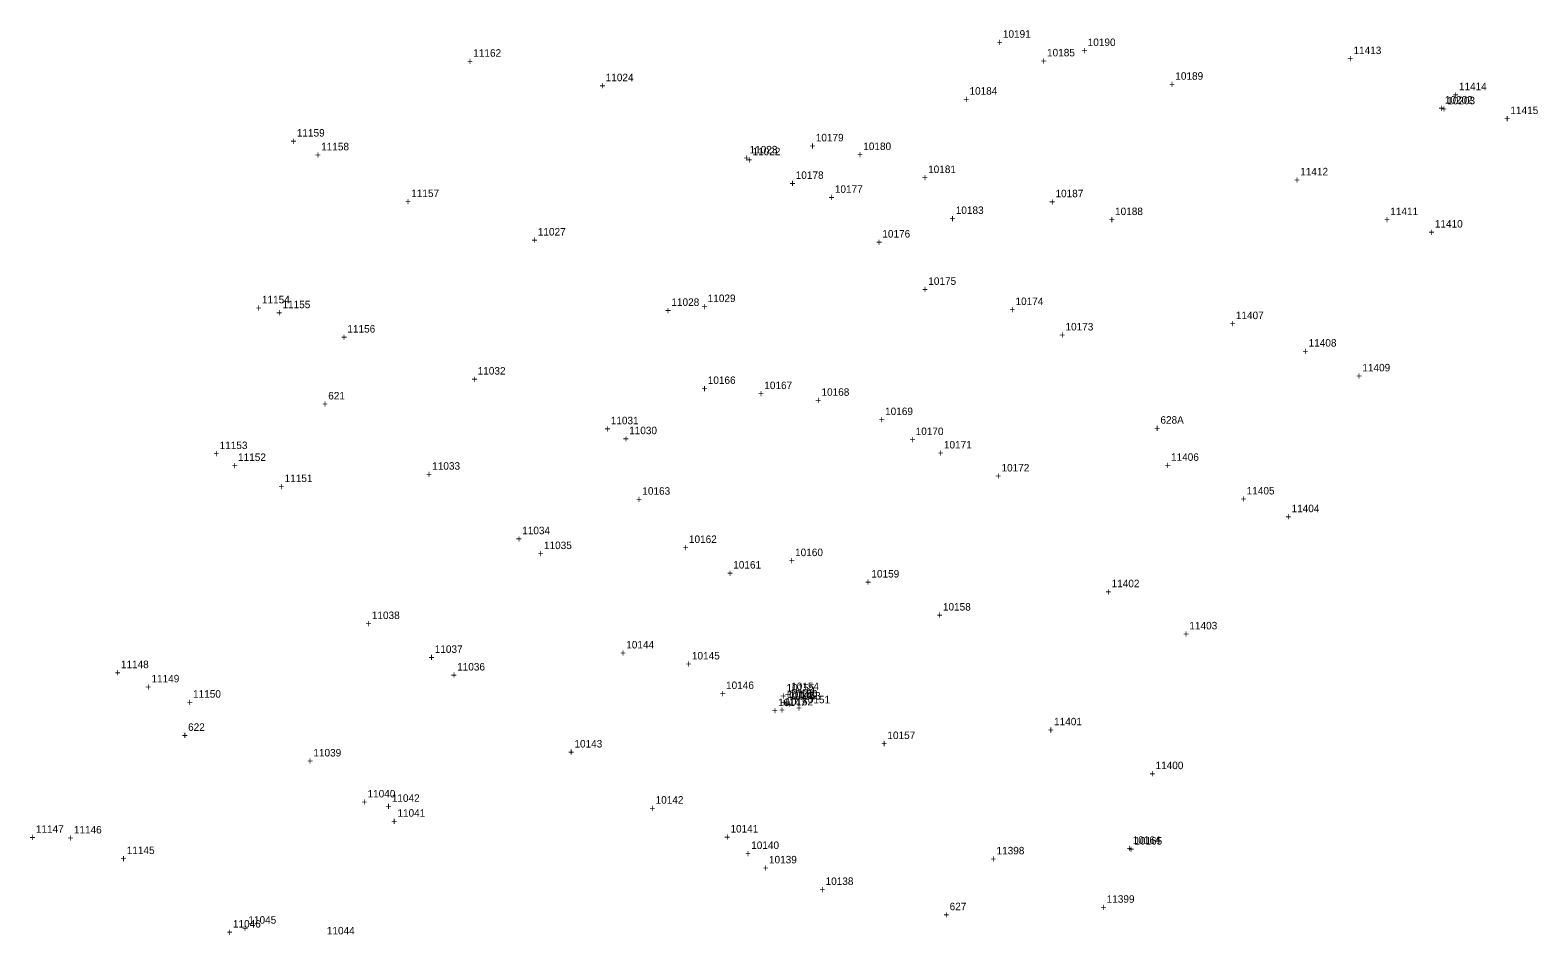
# Model space of a CAD drawing. Extents: x 1160051 to 1162814, y 614604 to 619560.
# Drawn here: x 1160247 to 1160750, y 615543 to 615845 of the extents above; entities that cross this region are included whole.
import ezdxf

# ---------------------------------------------------------------- set-up
doc = ezdxf.new("R2010")
doc.units = 0
for name, color, linetype in [('S_Control_Temp_Traverse', 7, 'Continuous'), ('S_Drainage_Culvert_Top', 7, 'Continuous'), ('S_Drainage_Invert', 7, 'Continuous'), ('S_Ground_Elevation', 7, 'Continuous'), ('S_Roadway_Drive_Paved', 7, 'Continuous'), ('S_Roadway_Monument', 7, 'Continuous'), ('S_Trees_TreeLine', 7, 'Continuous')]:
    doc.layers.add(name, color=color, linetype=linetype)

msp = doc.modelspace()

# ---------------------------------------------------------------- texts
at = {"layer": 'S_Control_Temp_Traverse'}
for s, p in [('621', (1160346.01, 615721.76)), ('+', (1160343.95, 615719.01)), ('628A', (1160623.65, 615713.68)), ('628', (1160623.65, 615713.68)), ('+', (1160621.59, 615710.93)), ('+', (1160621.59, 615710.93)), ('622', (1160299.24, 615611.15)), ('+', (1160297.18, 615608.4)), ('627', (1160553.33, 615551.28)), ('+', (1160551.27, 615548.53))]:
    msp.add_text(s, height=2.5, dxfattribs=at).set_placement(p)
at = {"layer": 'S_Drainage_Culvert_Top'}
for s, p in [('+', (1160716.49, 615817.77)), ('10202', (1160718.55, 615820.52)), ('11022', (1160487.57, 615803.28)), ('+', (1160485.51, 615800.53)), ('10150', (1160499.95, 615622.3)), ('+', (1160497.89, 615619.55)), ('10164', (1160614.38, 615573.44)), ('+', (1160612.32, 615570.69))]:
    msp.add_text(s, height=2.5, dxfattribs=at).set_placement(p)
at = {"layer": 'S_Drainage_Invert'}
for s, p in [('+', (1160717.26, 615817.52)), ('10203', (1160719.32, 615820.27)), ('11023', (1160486.58, 615803.9)), ('+', (1160484.52, 615801.15)), ('10149', (1160499.92, 615621.72)), ('+', (1160497.86, 615618.97)), ('10165', (1160614.95, 615573.19)), ('+', (1160612.89, 615570.44))]:
    msp.add_text(s, height=2.5, dxfattribs=at).set_placement(p)
at = {"layer": 'S_Ground_Elevation'}
for s, p in [('10191', (1160571.09, 615842.5)), ('+', (1160569.03, 615839.75)), ('10190', (1160599.39, 615839.74)), ('+', (1160392.33, 615833.42)), ('11162', (1160394.39, 615836.17)), ('+', (1160597.33, 615836.99)), ('+', (1160686.01, 615834.29)), ('11413', (1160688.07, 615837.04)), ('11024', (1160438.58, 615827.99)), ('10189', (1160628.62, 615828.48)), ('+', (1160436.52, 615825.24)), ('10184', (1160559.95, 615823.5)), ('+', (1160626.56, 615825.73)), ('11414', (1160723.23, 615824.97)), ('+', (1160557.89, 615820.75)), ('+', (1160721.17, 615822.22)), ('11415', (1160740.42, 615817.02)), ('+', (1160738.36, 615814.27)), ('11159', (1160335.52, 615809.5)), ('10179', (1160508.66, 615807.92)), ('+', (1160333.46, 615806.75)), ('11158', (1160343.64, 615804.92)), ('+', (1160506.6, 615805.17)), ('10180', (1160524.51, 615805.01)), ('+', (1160341.58, 615802.17)), ('+', (1160522.45, 615802.26)), ('10181', (1160546.15, 615797.35)), ('+', (1160499.92, 615792.64)), ('10178', (1160501.98, 615795.39)), ('+', (1160544.09, 615794.6)), ('+', (1160668.23, 615793.82)), ('11412', (1160670.29, 615796.57)), ('11157', (1160373.7, 615789.32)), ('+', (1160512.97, 615787.98)), ('10177', (1160515.03, 615790.73)), ('10187', (1160588.64, 615789.26)), ('+', (1160371.64, 615786.57)), ('+', (1160586.58, 615786.51)), ('10188', (1160608.52, 615783.3)), ('11411', (1160700.34, 615783.29)), ('+', (1160606.46, 615780.55)), ('+', (1160698.28, 615780.54)), ('11410', (1160715.21, 615779.14)), ('+', (1160413.87, 615773.73)), ('11027', (1160415.93, 615776.48)), ('+', (1160528.81, 615773.05)), ('10176', (1160530.87, 615775.8)), ('+', (1160713.15, 615776.39)), ('+', (1160544.14, 615757.27)), ('10175', (1160546.2, 615760.02)), ('11154', (1160323.88, 615753.85)), ('11155', (1160330.74, 615752.22)), ('11028', (1160460.49, 615752.99)), ('11029', (1160472.61, 615754.29)), ('10174', (1160575.31, 615753.29)), ('+', (1160321.82, 615751.1)), ('+', (1160328.68, 615749.47)), ('+', (1160458.43, 615750.24)), ('+', (1160470.55, 615751.54)), ('+', (1160573.25, 615750.54)), ('11407', (1160648.82, 615748.58)), ('11156', (1160352.39, 615744.08)), ('+', (1160589.92, 615742.05)), ('10173', (1160591.98, 615744.8)), ('+', (1160646.76, 615745.83)), ('+', (1160350.32, 615741.33)), ('11408', (1160673.1, 615739.4)), ('+', (1160671.04, 615736.65)), ('+', (1160393.8, 615727.32)), ('11032', (1160395.86, 615730.07)), ('10166', (1160472.62, 615726.94)), ('+', (1160688.97, 615728.39)), ('11409', (1160691.03, 615731.14)), ('+', (1160470.56, 615724.19)), ('+', (1160489.43, 615722.47)), ('10167', (1160491.49, 615725.22)), ('10168', (1160510.57, 615722.99)), ('+', (1160508.51, 615720.24)), ('10169', (1160531.79, 615716.55)), ('11031', (1160440.26, 615713.48)), ('+', (1160529.72, 615713.8)), ('+', (1160438.19, 615710.73)), ('+', (1160444.34, 615707.41)), ('11030', (1160446.4, 615710.16)), ('+', (1160307.7, 615702.45)), ('11153', (1160309.76, 615705.2)), ('11152', (1160315.91, 615701.24)), ('+', (1160549.36, 615702.65)), ('10171', (1160551.42, 615705.4)), ('11406', (1160627.19, 615701.28)), ('+', (1160313.85, 615698.49)), ('11033', (1160380.69, 615698.32)), ('10172', (1160570.63, 615697.72)), ('+', (1160625.13, 615698.53)), ('11151', (1160331.45, 615694.19)), ('+', (1160378.63, 615695.57)), ('+', (1160568.57, 615694.97)), ('+', (1160329.39, 615691.44)), ('+', (1160448.73, 615687.22)), ('10163', (1160450.79, 615689.97)), ('+', (1160650.37, 615687.3)), ('11405', (1160652.43, 615690.05)), ('11404', (1160667.4, 615684.13)), ('11034', (1160410.71, 615676.78)), ('+', (1160665.34, 615681.38)), ('+', (1160408.65, 615674.03)), ('11035', (1160417.98, 615671.82)), ('10162', (1160466.35, 615673.86)), ('+', (1160415.92, 615669.07)), ('+', (1160464.29, 615671.11)), ('+', (1160499.69, 615666.72)), ('10160', (1160501.76, 615669.47)), ('+', (1160479.06, 615662.57)), ('10161', (1160481.12, 615665.32)), ('10159', (1160527.22, 615662.33)), ('+', (1160525.16, 615659.58)), ('11402', (1160607.36, 615659.08)), ('10158', (1160551.08, 615651.31)), ('+', (1160605.3, 615656.33)), ('11038', (1160360.55, 615648.46)), ('+', (1160549.02, 615648.56)), ('+', (1160358.49, 615645.71)), ('+', (1160631.25, 615642.27)), ('11403', (1160633.32, 615645.02)), ('11037', (1160381.54, 615637.18)), ('10144', (1160445.43, 615638.65)), ('11148', (1160276.82, 615632.07)), ('+', (1160379.48, 615634.43)), ('11036', (1160389.01, 615631.29)), ('+', (1160443.37, 615635.9)), ('+', (1160465.28, 615632.22)), ('10145', (1160467.34, 615634.97)), ('+', (1160274.76, 615629.32)), ('11149', (1160287.02, 615627.34)), ('+', (1160386.95, 615628.54)), ('+', (1160284.96, 615624.59)), ('11150', (1160300.9, 615622.23)), ('+', (1160476.67, 615622.37)), ('10146', (1160478.73, 615625.12)), ('+', (1160496.84, 615621.56)), ('+', (1160498.4, 615622.02)), ('10155', (1160498.9, 615624.31)), ('10148', (1160499.12, 615622.07)), ('10154', (1160500.46, 615624.77)), ('10153', (1160501.04, 615621.6)), ('+', (1160298.84, 615619.48)), ('+', (1160494.04, 615616.68)), ('10147', (1160496.1, 615619.43)), ('+', (1160496.41, 615616.91)), ('+', (1160497.06, 615619.32)), ('10152', (1160498.47, 615619.66)), ('+', (1160498.98, 615618.85)), ('+', (1160502.09, 615617.59)), ('10151', (1160504.15, 615620.34)), ('11401', (1160588.17, 615613)), ('10157', (1160532.56, 615608.42)), ('+', (1160586.11, 615610.25)), ('11039', (1160341.04, 615602.59)), ('+', (1160426.08, 615602.84)), ('10143', (1160428.14, 615605.59)), ('+', (1160530.5, 615605.67)), ('+', (1160338.98, 615599.84)), ('11400', (1160622.02, 615598.36)), ('+', (1160619.96, 615595.61)), ('+', (1160357.05, 615586.17)), ('11040', (1160359.11, 615588.92)), ('10142', (1160455.23, 615586.85)), ('11041', (1160369.09, 615582.49)), ('+', (1160453.17, 615584.1)), ('11147', (1160248.45, 615577.11)), ('11146', (1160261.13, 615576.89)), ('+', (1160367.03, 615579.74)), ('10141', (1160480.2, 615577.22)), ('+', (1160246.39, 615574.36)), ('+', (1160259.07, 615574.14)), ('+', (1160478.14, 615574.47)), ('10140', (1160487.12, 615571.72)), ('+', (1160276.72, 615567.27)), ('11145', (1160278.78, 615570.02)), ('+', (1160485.06, 615568.97)), ('10139', (1160493.05, 615566.91)), ('+', (1160566.91, 615567.18)), ('11398', (1160568.97, 615569.93)), ('+', (1160490.99, 615564.16)), ('+', (1160509.88, 615556.96)), ('10138', (1160511.94, 615559.71)), ('+', (1160603.66, 615551.02)), ('11399', (1160605.72, 615553.77)), ('11045', (1160319.36, 615546.79)), ('+', (1160317.3, 615544.04)), ('11044', (1160345.54, 615543.22))]:
    msp.add_text(s, height=2.5, dxfattribs=at).set_placement(p)
at = {"layer": 'S_Roadway_Drive_Paved'}
for s, p in [('11046', (1160314.21, 615545.49)), ('+', (1160312.15, 615542.74))]:
    msp.add_text(s, height=2.5, dxfattribs=at).set_placement(p)
at = {"layer": 'S_Roadway_Monument'}
for s, p in [('11042', (1160367.2, 615587.46)), ('+', (1160365.14, 615584.71))]:
    msp.add_text(s, height=2.5, dxfattribs=at).set_placement(p)
at = {"layer": 'S_Trees_TreeLine'}
for s, p in [('+', (1160583.76, 615833.53)), ('10185', (1160585.82, 615836.28)), ('10183', (1160555.37, 615783.68)), ('+', (1160553.31, 615780.93)), ('+', (1160539.93, 615707.13)), ('10170', (1160541.99, 615709.88))]:
    msp.add_text(s, height=2.5, dxfattribs=at).set_placement(p)

doc.saveas('drawing.dxf')
